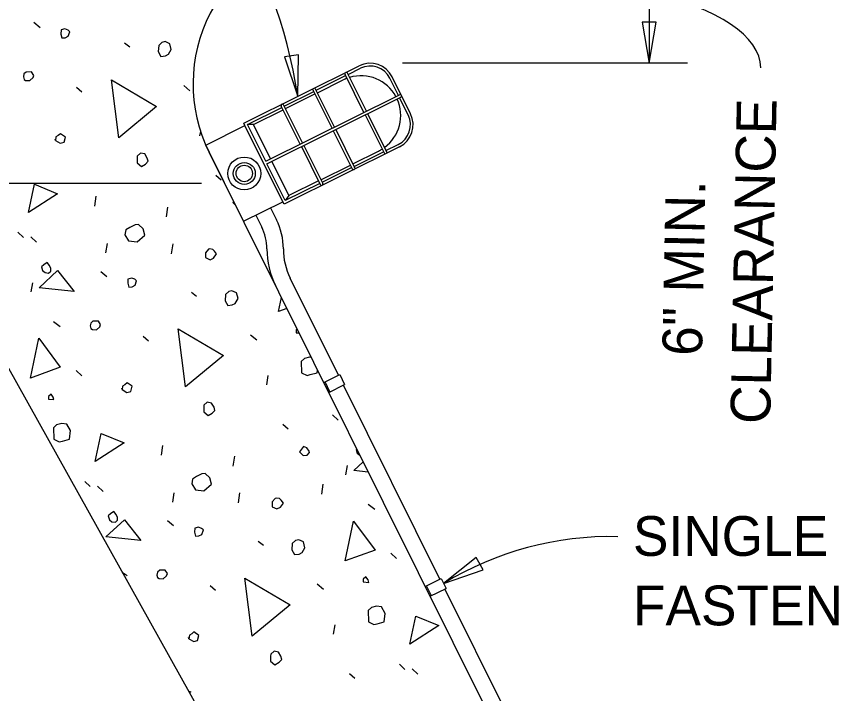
# Model space of a CAD drawing. Extents: x -1660015.2 to -1659984.9, y 2580594.2 to 2580616.7.
# Drawn here: x -1660011.876 to -1660008.753, y 2580610.058 to 2580612.631 of the extents above; entities that cross this region are included whole.
import ezdxf

# ---------------------------------------------------------------- set-up
doc = ezdxf.new("R2010")
doc.units = 0
for name, color, linetype in [('Default', 7, 'Continuous'), ('Miscellaneous', 7, 'Continuous'), ('Miscellaneous3', 7, 'Continuous'), ('SheetLines_dp', 7, 'Continuous'), ('SteelGirder', 7, 'Continuous')]:
    doc.layers.add(name, color=color, linetype=linetype)

msp = doc.modelspace()

# ---------------------------------------------------------------- linework, layer by layer
at = {"layer": 'Default'}
for p, q in [((-1660011.0123, 2580612.2256), (-1660010.5739, 2580612.4436)), ((-1660010.616, 2580612.4111), (-1660010.5693, 2580612.4343)), ((-1660010.7372, 2580612.3508), (-1660010.6253, 2580612.4064)), ((-1660010.5557, 2580612.2665), (-1660010.6276, 2580612.4111)), ((-1660010.5464, 2580612.2712), (-1660010.6183, 2580612.4157)), ((-1660010.4251, 2580612.3315), (-1660010.4576, 2580612.3968)), ((-1660010.3787, 2580612.2615), (-1660010.4483, 2580612.4014)), ((-1660010.9288, 2580612.081), (-1660010.4205, 2580612.3338)), ((-1660010.8585, 2580612.2905), (-1660010.7465, 2580612.3461)), ((-1660010.677, 2580612.2062), (-1660010.7489, 2580612.3508)), ((-1660010.6677, 2580612.2109), (-1660010.7395, 2580612.3554)), ((-1660010.9242, 2580612.0717), (-1660010.4159, 2580612.3245)), ((-1660010.7889, 2580612.1506), (-1660010.8608, 2580612.2951)), ((-1660010.388, 2580612.2568), (-1660010.4205, 2580612.3222)), ((-1660010.9984, 2580612.2209), (-1660010.8678, 2580612.2858)), ((-1660010.7982, 2580612.1459), (-1660010.8701, 2580612.2905)), ((-1660010.5511, 2580612.2572), (-1660010.4792, 2580612.1127)), ((-1660010.5418, 2580612.2619), (-1660010.4699, 2580612.1173)), ((-1660011.1569, 2580612.142), (-1660011.0077, 2580612.2163)), ((-1660011.0077, 2580612.2163), (-1660011.0123, 2580612.2256)), ((-1660010.8639, 2580611.9271), (-1660011.0077, 2580612.2163)), ((-1660010.9288, 2580612.081), (-1660010.9984, 2580612.2209)), ((-1660010.9751, 2580612.2208), (-1660010.9984, 2580612.2209)), ((-1660010.9102, 2580612.0903), (-1660010.9751, 2580612.2208)), ((-1660010.663, 2580612.2015), (-1660010.5911, 2580612.057)), ((-1660010.6723, 2580612.1969), (-1660010.6004, 2580612.0524)), ((-1660011.0132, 2580611.8529), (-1660011.1569, 2580612.142)), ((-1660010.7843, 2580612.1412), (-1660010.7124, 2580611.9967)), ((-1660010.4722, 2580612.1219), (-1660010.4255, 2580612.1452)), ((-1660010.4209, 2580612.1358), (-1660010.8593, 2580611.9178)), ((-1660010.7936, 2580612.1366), (-1660010.7217, 2580611.9921)), ((-1660010.5934, 2580612.0616), (-1660010.4815, 2580612.1173)), ((-1660010.8406, 2580611.9503), (-1660010.9055, 2580612.0809)), ((-1660010.8546, 2580611.9318), (-1660010.9242, 2580612.0717)), ((-1660010.7147, 2580612.0013), (-1660010.6028, 2580612.057)), ((-1660010.724, 2580611.9967), (-1660010.8546, 2580611.9318)), ((-1660011.0132, 2580611.8529), (-1660010.8639, 2580611.9271)), ((-1660010.8593, 2580611.9178), (-1660010.8639, 2580611.9271)), ((-1660010.8406, 2580611.9503), (-1660010.8546, 2580611.9318)), ((-1660010.9105, 2580611.9039), (-1660010.8881, 2580611.8589)), ((-1660010.9665, 2580611.8761), (-1660010.9441, 2580611.831)), ((-1660010.6524, 2580611.2679), (-1660010.8358, 2580611.6367)), ((-1660010.267, 2580610.4929), (-1660010.6338, 2580611.2305)), ((-1660009.8625, 2580609.6796), (-1660010.2484, 2580610.4556))]:
    msp.add_line(p, q, dxfattribs=at)
for radius in [0.0625, 0.0417, 0.0312]:
    msp.add_circle((-1660011.0104, 2580612.0346), radius, dxfattribs=at)
for centre, radius, start, end in [((-1660010.5322, 2580612.3597), 0.0937, 26.4422, 116.4422), ((-1660010.5322, 2580612.3597), 0.0833, 26.4422, 116.4422), ((-1660010.6229, 2580612.4134), 0.0052, 26.4422, 206.4423), ((-1660010.7442, 2580612.3531), 0.0052, 26.4422, 206.4423), ((-1660010.4182, 2580612.3291), 0.0052, 296.4087, 116.4422), ((-1660010.8655, 2580612.2928), 0.0052, 26.4422, 206.4423), ((-1660010.4626, 2580612.2197), 0.0833, 296.4422, 26.4422), ((-1660010.4626, 2580612.2197), 0.0937, 296.4422, 26.4422), ((-1660010.4745, 2580612.115), 0.0052, 206.4421, 26.4422), ((-1660010.5958, 2580612.0547), 0.0052, 206.4421, 26.4422), ((-1660010.717, 2580611.9944), 0.0052, 206.4421, 26.4422), ((-1660011.112, 2580611.7475), 0.25, 0.0537, 26.4422), ((-1660011.112, 2580611.7475), 0.1875, 0.0537, 26.4422), ((-1660010.612, 2580611.748), 0.3125, 180.0537, 206.4422), ((-1660010.612, 2580611.748), 0.25, 180.0537, 206.2933)]:
    msp.add_arc(centre, radius, start, end, dxfattribs=at)
at = {"layer": 'Miscellaneous'}
for p, q in [((-1660011.8095, 2580612.6092), (-1660011.7862, 2580612.5896)), ((-1660011.465, 2580612.5307), (-1660011.4453, 2580612.5153)), ((-1660010.7326, 2580612.3415), (-1660010.6346, 2580612.3902)), ((-1660011.6477, 2580612.3627), (-1660011.6274, 2580612.3448)), ((-1660011.2403, 2580612.3683), (-1660011.2169, 2580612.3487)), ((-1660010.8539, 2580612.2811), (-1660010.7419, 2580612.3368)), ((-1660010.9751, 2580612.2208), (-1660010.8632, 2580612.2765)), ((-1660011.1789, 2580612.1777), (-1660011.176, 2580612.1942)), ((-1660010.5981, 2580612.071), (-1660010.5001, 2580612.1197)), ((-1660010.7193, 2580612.0107), (-1660010.6074, 2580612.0663)), ((-1660011.1181, 2580612.0283), (-1660011.0978, 2580612.0105)), ((-1660010.7286, 2580612.006), (-1660010.8406, 2580611.9503)), ((-1660011.5782, 2580611.9102), (-1660011.5728, 2580611.9479)), ((-1660011.3059, 2580611.8693), (-1660011.3004, 2580611.907)), ((-1660011.8701, 2580611.8113), (-1660011.8491, 2580611.7911)), ((-1660011.8213, 2580611.7933), (-1660011.8003, 2580611.7731)), ((-1660011.5358, 2580611.7327), (-1660011.5298, 2580611.7679)), ((-1660011.2865, 2580611.7296), (-1660011.2811, 2580611.7673)), ((-1660010.9693, 2580611.7628), (-1660010.9691, 2580611.7644)), ((-1660011.5559, 2580611.6626), (-1660011.5325, 2580611.643)), ((-1660011.8196, 2580611.5842), (-1660011.8135, 2580611.6194)), ((-1660011.2113, 2580611.5841), (-1660011.1917, 2580611.5686)), ((-1660011.7352, 2580611.4722), (-1660011.7094, 2580611.4532)), ((-1660010.9866, 2580611.4217), (-1660010.9633, 2580611.4021)), ((-1660011.3941, 2580611.4161), (-1660011.3738, 2580611.3982)), ((-1660011.649, 2580611.2856), (-1660011.628, 2580611.2654)), ((-1660010.9252, 2580611.2311), (-1660010.9191, 2580611.2664)), ((-1660010.6747, 2580611.1171), (-1660010.6537, 2580611.0968)), ((-1660010.8645, 2580611.0817), (-1660010.8442, 2580611.0639)), ((-1660011.3246, 2580610.9636), (-1660011.3192, 2580611.0013)), ((-1660011.0522, 2580610.9227), (-1660011.0468, 2580610.9604)), ((-1660010.6242, 2580610.8899), (-1660010.6181, 2580610.9252)), ((-1660011.6164, 2580610.8647), (-1660011.5955, 2580610.8445)), ((-1660011.5676, 2580610.8467), (-1660011.5467, 2580610.8265)), ((-1660010.7157, 2580610.8162), (-1660010.7103, 2580610.8539)), ((-1660011.2822, 2580610.786), (-1660011.2761, 2580610.8213)), ((-1660011.0329, 2580610.783), (-1660011.0275, 2580610.8207)), ((-1660010.5398, 2580610.7779), (-1660010.514, 2580610.7589)), ((-1660011.3022, 2580610.716), (-1660011.2789, 2580610.6964)), ((-1660010.9577, 2580610.6375), (-1660010.938, 2580610.622)), ((-1660010.4536, 2580610.5914), (-1660010.4326, 2580610.5711)), ((-1660011.474, 2580610.52), (-1660011.4558, 2580610.5066)), ((-1660011.1404, 2580610.4695), (-1660011.1201, 2580610.4516)), ((-1660010.733, 2580610.4751), (-1660010.7096, 2580610.4555)), ((-1660010.6716, 2580610.2845), (-1660010.6655, 2580610.3198)), ((-1660010.421, 2580610.1705), (-1660010.4001, 2580610.1502)), ((-1660010.3722, 2580610.1525), (-1660010.3513, 2580610.1322)), ((-1660010.6109, 2580610.1351), (-1660010.5905, 2580610.1173))]:
    msp.add_line(p, q, dxfattribs=at)
for points in [[(-1660011.7069, 2580612.5642), (-1660011.703, 2580612.5497), (-1660011.6903, 2580612.5506), (-1660011.6789, 2580612.5562), (-1660011.6731, 2580612.5733), (-1660011.6799, 2580612.5792), (-1660011.6915, 2580612.5839), (-1660011.7059, 2580612.58), (-1660011.7069, 2580612.5642)], [(-1660011.3356, 2580612.5213), (-1660011.3371, 2580612.4977), (-1660011.3271, 2580612.4796), (-1660011.3095, 2580612.4818), (-1660011.2981, 2580612.4874), (-1660011.2875, 2580612.5058), (-1660011.2933, 2580612.5275), (-1660011.311, 2580612.5357), (-1660011.3231, 2580612.5325), (-1660011.3356, 2580612.5213)], [(-1660011.8471, 2580612.3921), (-1660011.841, 2580612.3885), (-1660011.8252, 2580612.3876), (-1660011.8127, 2580612.3987), (-1660011.8098, 2580612.4072), (-1660011.8185, 2580612.4204), (-1660011.8391, 2580612.4201), (-1660011.8475, 2580612.4127), (-1660011.8497, 2580612.4017), (-1660011.8471, 2580612.3921)], [(-1660011.4874, 2580612.1701), (-1660011.5154, 2580612.3904), (-1660011.3433, 2580612.289), (-1660011.4874, 2580612.1701)], [(-1660011.728, 2580612.16), (-1660011.7096, 2580612.1494), (-1660011.6951, 2580612.1533), (-1660011.69, 2580612.1728), (-1660011.709, 2580612.1858), (-1660011.7174, 2580612.1784), (-1660011.7264, 2580612.1734), (-1660011.728, 2580612.16), (-1660011.7293, 2580612.1648)], [(-1660011.4176, 2580612.093), (-1660011.4179, 2580612.0748), (-1660011.4013, 2580612.0612), (-1660011.3857, 2580612.0705), (-1660011.3755, 2580612.081), (-1660011.3788, 2580612.0931), (-1660011.3881, 2580612.1087), (-1660011.4046, 2580612.1121), (-1660011.4171, 2580612.1009), (-1660011.4176, 2580612.093)], [(-1660011.8307, 2580611.8866), (-1660011.8077, 2580611.9937), (-1660011.7203, 2580611.9576), (-1660011.8307, 2580611.8866)], [(-1660011.0506, 2580611.9282), (-1660011.0539, 2580611.9239)], [(-1660011.0539, 2580611.9239), (-1660011.043, 2580611.9129)], [(-1660011.4636, 2580611.8012), (-1660011.4499, 2580611.779), (-1660011.4177, 2580611.7747), (-1660011.3884, 2580611.8006), (-1660011.3949, 2580611.8248), (-1660011.4121, 2580611.8409), (-1660011.4249, 2580611.84), (-1660011.4453, 2580611.8294), (-1660011.4609, 2580611.82), (-1660011.4636, 2580611.8012)], [(-1660011.158, 2580611.7329), (-1660011.1583, 2580611.7148), (-1660011.1406, 2580611.7066), (-1660011.1268, 2580611.7129), (-1660011.1155, 2580611.7288), (-1660011.1236, 2580611.7396), (-1660011.1304, 2580611.7455), (-1660011.1413, 2580611.7478), (-1660011.1461, 2580611.7465), (-1660011.158, 2580611.7329)], [(-1660011.7767, 2580611.6655), (-1660011.7668, 2580611.6578), (-1660011.7535, 2580611.6562), (-1660011.7451, 2580611.6636), (-1660011.7453, 2580611.6739), (-1660011.7509, 2580611.6854), (-1660011.759, 2580611.6962), (-1660011.7722, 2580611.6874), (-1660011.7806, 2580611.68), (-1660011.7767, 2580611.6655)], [(-1660011.7901, 2580611.5998), (-1660011.7197, 2580611.6653), (-1660011.6571, 2580611.5863), (-1660011.7901, 2580611.5998)], [(-1660011.4533, 2580611.6176), (-1660011.4494, 2580611.6031), (-1660011.4366, 2580611.6039), (-1660011.4252, 2580611.6096), (-1660011.4194, 2580611.6267), (-1660011.4262, 2580611.6326), (-1660011.4378, 2580611.6373), (-1660011.4523, 2580611.6334), (-1660011.4533, 2580611.6176)], [(-1660011.082, 2580611.5747), (-1660011.0834, 2580611.5511), (-1660011.0734, 2580611.533), (-1660011.0559, 2580611.5352), (-1660011.0444, 2580611.5408), (-1660011.0338, 2580611.5592), (-1660011.0397, 2580611.5809), (-1660011.0574, 2580611.5891), (-1660011.0695, 2580611.5859), (-1660011.082, 2580611.5747)], [(-1660010.8808, 2580611.5096), (-1660010.8693, 2580611.5637)], [(-1660010.8482, 2580611.5213), (-1660010.8808, 2580611.5096)], [(-1660011.5935, 2580611.4455), (-1660011.5873, 2580611.4419), (-1660011.5716, 2580611.441), (-1660011.559, 2580611.4521), (-1660011.5561, 2580611.4606), (-1660011.5648, 2580611.4738), (-1660011.5855, 2580611.4735), (-1660011.5938, 2580611.4661), (-1660011.5961, 2580611.4551), (-1660011.5935, 2580611.4455)], [(-1660011.2338, 2580611.2235), (-1660011.2617, 2580611.4438), (-1660011.0896, 2580611.3423), (-1660011.2338, 2580611.2235)], [(-1660010.8091, 2580611.4426), (-1660010.8129, 2580611.4398), (-1660010.8127, 2580611.4295)], [(-1660010.8127, 2580611.4295), (-1660010.8021, 2580611.4284)], [(-1660011.8226, 2580611.2572), (-1660011.7905, 2580611.4082), (-1660011.7092, 2580611.298), (-1660011.8226, 2580611.2572)], [(-1660010.7561, 2580611.3361), (-1660010.7621, 2580611.3369), (-1660010.7814, 2580611.3318), (-1660010.7939, 2580611.3206)], [(-1660010.7939, 2580611.3206), (-1660010.7926, 2580611.277), (-1660010.7718, 2580611.267), (-1660010.7597, 2580611.2703), (-1660010.7332, 2580611.2774), (-1660010.7318, 2580611.2873)], [(-1660011.4743, 2580611.2134), (-1660011.456, 2580611.2028), (-1660011.4415, 2580611.2067), (-1660011.4364, 2580611.2261), (-1660011.4554, 2580611.2392), (-1660011.4637, 2580611.2318), (-1660011.4728, 2580611.2267), (-1660011.4743, 2580611.2134), (-1660011.4756, 2580611.2182)], [(-1660011.7545, 2580611.1771), (-1660011.7333, 2580611.1751), (-1660011.7358, 2580611.1847), (-1660011.7439, 2580611.1955), (-1660011.7547, 2580611.1874), (-1660011.7545, 2580611.1771)], [(-1660011.1639, 2580611.1464), (-1660011.1642, 2580611.1282), (-1660011.1476, 2580611.1146), (-1660011.132, 2580611.1239), (-1660011.1219, 2580611.1344), (-1660011.1251, 2580611.1465), (-1660011.1345, 2580611.1621), (-1660011.1509, 2580611.1655), (-1660011.1635, 2580611.1543), (-1660011.1639, 2580611.1464)], [(-1660011.7357, 2580611.0683), (-1660011.7344, 2580611.0247), (-1660011.7136, 2580611.0147), (-1660011.7015, 2580611.0179), (-1660011.6749, 2580611.025), (-1660011.6706, 2580611.0573), (-1660011.685, 2580611.0819), (-1660011.7038, 2580611.0846), (-1660011.7232, 2580611.0794), (-1660011.7357, 2580611.0683)], [(-1660011.5771, 2580610.94), (-1660011.554, 2580611.0471), (-1660011.4667, 2580611.011), (-1660011.5771, 2580610.94)], [(-1660010.8003, 2580610.9773), (-1660010.7861, 2580610.963), (-1660010.771, 2580610.9644), (-1660010.7632, 2580610.9743), (-1660010.7645, 2580610.9791), (-1660010.7732, 2580610.9923), (-1660010.7848, 2580610.997), (-1660010.7926, 2580610.9871), (-1660010.8003, 2580610.9773)], [(-1660010.5829, 2580610.9878), (-1660010.5851, 2580610.9858), (-1660010.5813, 2580610.9713)], [(-1660010.5813, 2580610.9713), (-1660010.5714, 2580610.9636), (-1660010.5708, 2580610.9635)], [(-1660010.5947, 2580610.9056), (-1660010.5586, 2580610.9391)], [(-1660011.21, 2580610.8546), (-1660011.1963, 2580610.8324), (-1660011.164, 2580610.8281), (-1660011.1348, 2580610.854), (-1660011.1412, 2580610.8782), (-1660011.1585, 2580610.8943), (-1660011.1712, 2580610.8934), (-1660011.1916, 2580610.8828), (-1660011.2073, 2580610.8734), (-1660011.21, 2580610.8546)], [(-1660010.5392, 2580610.8999), (-1660010.5947, 2580610.9056)], [(-1660010.9044, 2580610.7863), (-1660010.9047, 2580610.7681), (-1660010.887, 2580610.76), (-1660010.8731, 2580610.7662), (-1660010.8619, 2580610.7822), (-1660010.8699, 2580610.793), (-1660010.8767, 2580610.7989), (-1660010.8877, 2580610.8012), (-1660010.8925, 2580610.7999), (-1660010.9044, 2580610.7863)], [(-1660011.523, 2580610.7189), (-1660011.5132, 2580610.7112), (-1660011.4998, 2580610.7096), (-1660011.4915, 2580610.717), (-1660011.4916, 2580610.7273), (-1660011.4973, 2580610.7388), (-1660011.5054, 2580610.7495), (-1660011.5185, 2580610.7408), (-1660011.5269, 2580610.7334), (-1660011.523, 2580610.7189)], [(-1660011.5365, 2580610.6532), (-1660011.466, 2580610.7187), (-1660011.4034, 2580610.6397), (-1660011.5365, 2580610.6532)], [(-1660010.6271, 2580610.563), (-1660010.5951, 2580610.7139), (-1660010.5138, 2580610.6037), (-1660010.6271, 2580610.563)], [(-1660011.1996, 2580610.671), (-1660011.1957, 2580610.6565), (-1660011.183, 2580610.6573), (-1660011.1716, 2580610.663), (-1660011.1658, 2580610.6801), (-1660011.1726, 2580610.686), (-1660011.1842, 2580610.6907), (-1660011.1987, 2580610.6868), (-1660011.1996, 2580610.671)], [(-1660010.8284, 2580610.6281), (-1660010.8298, 2580610.6045), (-1660010.8198, 2580610.5864), (-1660010.8022, 2580610.5885), (-1660010.7908, 2580610.5942), (-1660010.7802, 2580610.6126), (-1660010.786, 2580610.6343), (-1660010.8037, 2580610.6425), (-1660010.8158, 2580610.6393), (-1660010.8284, 2580610.6281)], [(-1660011.3398, 2580610.4988), (-1660011.3337, 2580610.4953), (-1660011.3179, 2580610.4944), (-1660011.3054, 2580610.5055), (-1660011.3025, 2580610.514), (-1660011.3112, 2580610.5272), (-1660011.3318, 2580610.5269), (-1660011.3402, 2580610.5195), (-1660011.3424, 2580610.5085), (-1660011.3398, 2580610.4988)], [(-1660010.9801, 2580610.2769), (-1660011.0081, 2580610.4972), (-1660010.836, 2580610.3957), (-1660010.9801, 2580610.2769)], [(-1660010.5591, 2580610.4829), (-1660010.5378, 2580610.4808), (-1660010.5404, 2580610.4905), (-1660010.5485, 2580610.5012), (-1660010.5593, 2580610.4932), (-1660010.5591, 2580610.4829)], [(-1660010.5403, 2580610.374), (-1660010.5389, 2580610.3304), (-1660010.5182, 2580610.3204), (-1660010.5061, 2580610.3237), (-1660010.4795, 2580610.3308), (-1660010.4752, 2580610.363), (-1660010.4896, 2580610.3876), (-1660010.5084, 2580610.3903), (-1660010.5277, 2580610.3852), (-1660010.5403, 2580610.374)], [(-1660010.3817, 2580610.2457), (-1660010.3586, 2580610.3528), (-1660010.2713, 2580610.3167), (-1660010.3817, 2580610.2457)], [(-1660011.2207, 2580610.2668), (-1660011.2023, 2580610.2562), (-1660011.1878, 2580610.26), (-1660011.1827, 2580610.2795), (-1660011.2017, 2580610.2926), (-1660011.2101, 2580610.2851), (-1660011.2191, 2580610.2801), (-1660011.2207, 2580610.2668), (-1660011.222, 2580610.2716)], [(-1660010.9103, 2580610.1998), (-1660010.9106, 2580610.1816), (-1660010.894, 2580610.168), (-1660010.8784, 2580610.1773), (-1660010.8683, 2580610.1878), (-1660010.8715, 2580610.1999), (-1660010.8808, 2580610.2155), (-1660010.8973, 2580610.2188), (-1660010.9098, 2580610.2077), (-1660010.9103, 2580610.1998)], [(-1660011.2217, 2580610.0679), (-1660011.2131, 2580610.0644), (-1660011.218, 2580610.0612)]]:
    msp.add_lwpolyline(points, dxfattribs=at)
for start, end in [(110.5219, 116.4422), (28.4157, 106.5369), (306.3475, 24.4687), (296.4422, 302.3625)]:
    msp.add_arc((-1660010.5673, 2580612.2549), 0.151, start, end, dxfattribs=at)
at = {"layer": 'Miscellaneous3'}
for p, q in [((-1660009.5517, 2580608.9143), (-1660011.144, 2580612.116)), ((-1660008.7906, 2580605.7114), (-1660012.2404, 2580611.8935))]:
    msp.add_line(p, q, dxfattribs=at)
msp.add_arc((-1660010.6217, 2580612.3757), 0.5833, 98.8325, 206.4422, dxfattribs=at)
at = {"layer": 'SheetLines_dp'}
for p, q in [((-1660009.4721, 2580612.9853), (-1660009.4721, 2580612.4534)), ((-1660009.3262, 2580612.4534), (-1660010.4096, 2580612.4534)), ((-1660013.0517, 2580611.9975), (-1660011.1723, 2580611.9975))]:
    msp.add_line(p, q, dxfattribs=at)
for points in [[(-1660009.4721, 2580612.4533), (-1660009.4456, 2580612.6095), (-1660009.4985, 2580612.6095)], [(-1660010.8071, 2580612.3276), (-1660010.8048, 2580612.4859), (-1660010.8571, 2580612.4779)], [(-1660010.2531, 2580610.4765), (-1660010.1034, 2580610.5284), (-1660010.1289, 2580610.5748)]]:
    msp.add_lwpolyline(points, close=True, dxfattribs=at)
for centre, major_axis, ratio, start_param, end_param in [((-1660011.5969, 2580612.0226), (0.0174, -1.3204), 0.616683, 1.795781, 3.022833), ((-1660009.8313, 2580612.436), (-0.7827, 0), 0.407451, 3.141527, 4.235533), ((-1660009.6264, 2580609.3417), (-0.0346, -1.3124), 0.953713, 3.141601, 3.693377)]:
    msp.add_ellipse(centre, major_axis=major_axis, ratio=ratio, start_param=start_param, end_param=end_param, dxfattribs=at)
at = {"layer": 'SteelGirder'}
for p, q in [((-1660010.7084, 2580611.24), (-1660010.6477, 2580611.2702)), ((-1660010.6477, 2580611.2702), (-1660010.6292, 2580611.2328)), ((-1660010.6851, 2580611.205), (-1660010.7037, 2580611.2424)), ((-1660010.6898, 2580611.2027), (-1660010.6292, 2580611.2328)), ((-1660010.323, 2580610.4651), (-1660010.2623, 2580610.4952)), ((-1660010.2623, 2580610.4952), (-1660010.2438, 2580610.4579)), ((-1660010.2997, 2580610.4301), (-1660010.3183, 2580610.4674)), ((-1660010.3044, 2580610.4278), (-1660010.2438, 2580610.4579))]:
    msp.add_line(p, q, dxfattribs=at)

# ---------------------------------------------------------------- texts
at = {"layer": 'SheetLines_dp'}
for s, p in [('CLEARANCE', (-1660009.0127, 2580611.0815)), ('6" MIN.', (-1660009.2716, 2580611.3405))]:
    msp.add_text(s, height=0.1512, rotation=88.8542, dxfattribs=at).set_placement(p)
for s, p in [('SINGLE HOLE STRAPS WITH', (-1660009.5339, 2580610.5814)), ('FASTENERS (SEE NOTE 8, TYP.)', (-1660009.5339, 2580610.3174))]:
    msp.add_text(s, height=0.1512, dxfattribs=at).set_placement(p)

doc.saveas('drawing.dxf')
